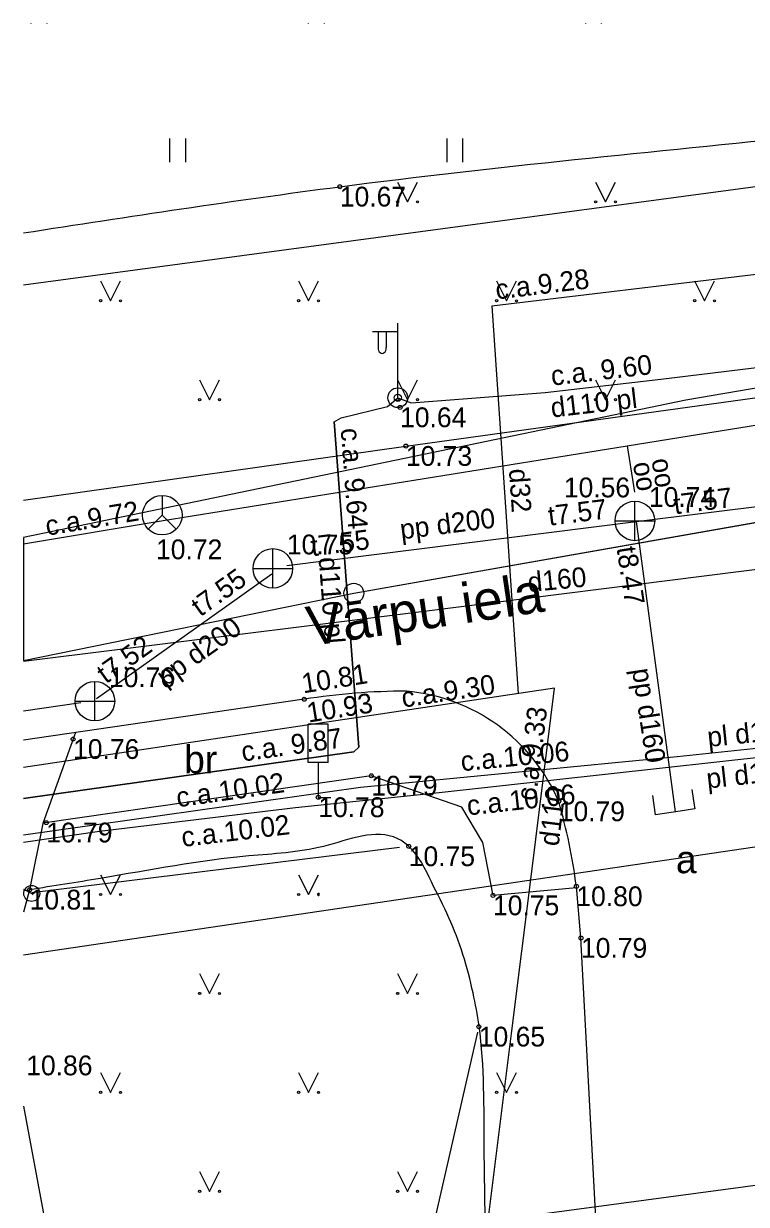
# Model space of a CAD drawing. Extents: x 502312.8 to 502402.4, y 308528.5 to 308602.
# Drawn here: x 502312.81 to 502331.06, y 308572.17 to 308602 of the extents above; entities that cross this region are included whole.
import ezdxf

# ---------------------------------------------------------------- set-up
doc = ezdxf.new("R2010")
doc.units = 0
for name, color, linetype in [('10', 7, 'Continuous'), ('24', 7, 'Continuous'), ('38', 7, 'Continuous'), ('APGR_SARK_####_####_#', 7, 'Continuous'), ('APGS_ACRL_####_####_#', 7, 'Continuous'), ('APGS_ACRL_####_TKST_#', 7, 'Continuous'), ('APGS_ELEM_####_####_#', 7, 'Continuous'), ('APGS_VADP_ZSPR_####_I', 7, 'Continuous'), ('CELI_CAPM_####_####_#', 7, 'Continuous'), ('CELI_CMAL_####_####_#', 7, 'Continuous'), ('CELI_CSEG_####_TKST_#', 7, 'Continuous'), ('CELI_ELEM_####_####_#', 7, 'Continuous'), ('CELI_IELA_####_TKST_#', 7, 'Continuous'), ('CELI_SEGL_####_####_#', 7, 'Continuous'), ('ELEK_ACRL_####_####_#', 7, 'Continuous'), ('ELEK_ACRL_####_TKST_#', 7, 'Continuous'), ('ELEK_VADP_VSPR_####_I', 7, 'Continuous'), ('ELEK_VADP_ZSPR_####_I', 7, 'Continuous'), ('GAZE_VADP_VSP2_####_#', 7, 'Continuous'), ('GAZE_VADP_VSP2_TKST_#', 7, 'Continuous'), ('NORB_ELEM_####_####_#', 7, 'Continuous'), ('NORB_ZOGS_BARJ_####_#', 7, 'Continuous'), ('NORB_ZOGS_ZSTP_####_#', 7, 'Continuous'), ('RELJ_AATZ_####_TKST_#', 7, 'Continuous'), ('RELJ_ELEM_####_####_#', 7, 'Continuous'), ('SAKK_ELEM_####_####_#', 7, 'Continuous'), ('SAKK_ELEM_####_TKST_#', 7, 'Continuous'), ('SAKK_IZVK_####_TKST_#', 7, 'Continuous'), ('SAKK_KKAN_####_####_#', 7, 'Continuous'), ('SAKK_KKAN_####_TKST_#', 7, 'Continuous'), ('SKAN_ELEM_####_####_#', 7, 'Continuous'), ('SKAN_ELEM_PAST_TKST_#', 7, 'Continuous'), ('SKAN_VADP_PAST_####_I', 7, 'Continuous'), ('SKAN_VADP_PAST_TKST_I', 7, 'Continuous'), ('TERT_ELEM_####_####_#', 7, 'Continuous'), ('TERT_KONT_####_####_#', 7, 'Continuous'), ('UDTK_VADP_UDEN_####_I', 7, 'Continuous'), ('UDTK_VADP_UDEN_TKST_I', 7, 'Continuous')]:
    doc.layers.add(name, color=color, linetype=linetype)

msp = doc.modelspace()

# ---------------------------------------------------------------- linework, layer by layer
at = {"layer": '10'}
msp.add_circle((502321.144, 308587.612), 0.25, dxfattribs=at)
at = {"layer": '24'}
for p, q in [((502321.144, 308587.612), (502337.181, 308590.44)), ((502312.806, 308585.911), (502321.144, 308587.612)), ((502335.708, 308581.855), (502312.806, 308578.464))]:
    msp.add_line(p, q, dxfattribs=at)
at = {"layer": '38'}
msp.add_line((502312.806, 308589.016), (502312.806, 308585.911), dxfattribs=at)
msp.add_lwpolyline([(502312.806, 308585.911), (502321.144, 308587.612), (502337.181, 308590.44), (502351.582, 308592.356), (502382.507, 308595.627), (502382.531, 308595.63), (502383.93, 308595.78), (502383.493, 308598.901), (502376.9, 308598.344), (502359.324, 308596.701), (502339.771, 308594.239), (502329.531, 308592.488), (502312.806, 308589.016)], dxfattribs=at)
at = {"layer": 'APGR_SARK_####_####_#'}
for p, q in [((502312.806, 308595.403), (502361.947, 308602.001)), ((502312.806, 308570.179), (502363.114, 308576.934))]:
    msp.add_line(p, q, dxfattribs=at)
at = {"layer": 'APGS_ACRL_####_####_#'}
msp.add_line((502325.976, 308592.683), (502328.899, 308593.021), dxfattribs=at)
msp.add_lwpolyline([(502320.647, 308591.944), (502321.27, 308583.722), (502321.142, 308583.604), (502312.806, 308582.421)], dxfattribs=at)
at = {"layer": 'APGS_ELEM_####_####_#'}
for p, q in [((502322.255, 308592.549), (502322.255, 308594.432)), ((502322.255, 308594.216), (502321.62, 308594.211)), ((502321.755, 308594.212), (502321.755, 308593.82)), ((502321.965, 308594.214), (502321.965, 308593.82))]:
    msp.add_line(p, q, dxfattribs=at)
for radius in [0.25, 0.09]:
    msp.add_circle((502322.255, 308592.549), radius, dxfattribs=at)
msp.add_ellipse((502321.86, 308593.82), major_axis=(0, 0.151), ratio=0.695971, start_param=1.570796, end_param=4.712389, dxfattribs=at)
at = {"layer": 'APGS_VADP_ZSPR_####_I'}
for p, q in [((502325.976, 308592.683), (502328.899, 308593.021)), ((502321.27, 308583.722), (502320.647, 308591.944))]:
    msp.add_line(p, q, dxfattribs=at)
for points in [[(502328.899, 308593.021), (502345.961, 308595.098), (502354.788, 308596.247), (502359.02, 308596.899)], [(502321.996, 308592.329), (502322.255, 308592.549), (502322.59, 308592.422)], [(502322.59, 308592.422), (502325.976, 308592.683)], [(502320.647, 308591.944), (502320.822, 308592.044), (502321.996, 308592.329)], [(502312.806, 308582.421), (502321.142, 308583.604), (502321.27, 308583.722)]]:
    msp.add_lwpolyline(points, dxfattribs=at)
at = {"layer": 'CELI_CAPM_####_####_#'}
for points in [[(502312.806, 308589.961), (502322.46, 308591.329), (502333.461, 308592.851), (502346.075, 308594.464), (502354.016, 308595.225), (502359.019, 308595.646), (502368.001, 308596.15), (502374.084, 308596.461), (502389.008, 308597.854), (502397.381, 308598.824), (502402.407, 308599.392)], [(502319.891, 308584.932), (502312.806, 308583.899)], [(502312.957, 308580.12), (502312.806, 308579.555)], [(502322.863, 308528.536), (502323.443, 308530.946), (502325.163, 308540.207), (502326.683, 308549.996), (502327.505, 308559.246), (502327.386, 308569.461), (502326.881, 308578.901), (502326.764, 308580.205)], [(502312.806, 308574.649), (502313.726, 308569.672), (502314.559, 308564.701), (502312.806, 308564.738)]]:
    msp.add_lwpolyline(points, dxfattribs=at)
for centre, radius, start, end in [((502322.492, 308568.529), 16.608, 90.0741, 99.0119), ((502322.065, 308580.526), 4.629, 23.2192, 84.9708), ((502311.98, 308578.258), 14.912, 7.5007, 15.9293)]:
    msp.add_arc(centre, radius, start, end, dxfattribs=at)
at = {"layer": 'CELI_CMAL_####_####_#'}
for points in [[(502314.114, 308584.09), (502313.289, 308581.796), (502312.957, 308580.12)], [(502326.769, 308580.165), (502324.659, 308579.975), (502324.4, 308581.314), (502323.874, 308582.21), (502321.585, 308582.998), (502313.291, 308581.803)]]:
    msp.add_lwpolyline(points, dxfattribs=at)
at = {"layer": 'CELI_ELEM_####_####_#'}
for p, q in [((502320.493, 308584.301), (502319.993, 308584.301)), ((502319.993, 308583.332), (502319.993, 308584.301)), ((502320.493, 308583.332), (502320.493, 308584.301)), ((502320.493, 308583.332), (502319.993, 308583.332)), ((502320.247, 308583.332), (502320.247, 308582.454)), ((502320.247, 308582.454), (502320.562, 308582.454))]:
    msp.add_line(p, q, dxfattribs=at)
at = {"layer": 'CELI_SEGL_####_####_#'}
msp.add_lwpolyline([(502312.806, 308580.102), (502312.957, 308580.12)], dxfattribs=at)
at = {"layer": 'ELEK_ACRL_####_####_#'}
for points in [[(502312.806, 308581.506), (502314.65, 308581.767), (502321.314, 308582.715), (502329.307, 308583.49), (502335.866, 308584.18), (502339.262, 308584.609), (502345.983, 308585.426), (502351.131, 308585.924)], [(502312.806, 308581.319), (502314.719, 308581.602), (502319.674, 308582.194), (502323.299, 308582.577), (502335.948, 308583.975), (502339.276, 308584.42), (502343.854, 308584.946)]]:
    msp.add_lwpolyline(points, dxfattribs=at)
at = {"layer": 'ELEK_VADP_VSPR_####_I'}
msp.add_lwpolyline([(502312.806, 308581.319), (502314.719, 308581.602), (502319.674, 308582.194), (502323.299, 308582.577), (502335.948, 308583.975), (502339.276, 308584.42), (502343.828, 308584.943)], dxfattribs=at)
at = {"layer": 'ELEK_VADP_ZSPR_####_I'}
msp.add_lwpolyline([(502312.806, 308581.506), (502314.65, 308581.767), (502321.314, 308582.715), (502329.307, 308583.49), (502335.866, 308584.18), (502339.262, 308584.609), (502345.983, 308585.426), (502351.131, 308585.924)], dxfattribs=at)
at = {"layer": 'GAZE_VADP_VSP2_####_#'}
msp.add_lwpolyline([(502312.806, 308585.897), (502315.165, 308586.191), (502322.988, 308587.165), (502330.855, 308588.157), (502338.722, 308589.148), (502339.59, 308589.258)], dxfattribs=at)
at = {"layer": 'NORB_ELEM_####_####_#'}
msp.add_circle((502313.01, 308580.025), 0.202, dxfattribs=at)
at = {"layer": 'NORB_ZOGS_BARJ_####_#'}
msp.add_lwpolyline([(502312.806, 308580.135), (502313.01, 308580.025)], dxfattribs=at)
at = {"layer": 'NORB_ZOGS_ZSTP_####_#'}
for points in [[(502322.296, 308581.187), (502313.015, 308580.038)], [(502313.304, 308528.536), (502319.831, 308557.078), (502324.272, 308576.524)]]:
    msp.add_lwpolyline(points, dxfattribs=at)
at = {"layer": 'RELJ_ELEM_####_####_#'}
for centre in [(502320.791, 308597.881), (502322.313, 308592.306), (502322.46, 308591.329), (502319.891, 308584.932), (502314.055, 308583.925), (502321.585, 308582.998), (502320.247, 308582.454), (502326.319, 308582.351), (502313.377, 308581.815), (502322.532, 308581.216), (502312.957, 308580.12), (502324.659, 308579.975), (502326.764, 308580.205), (502326.881, 308578.901), (502324.301, 308576.659)]:
    msp.add_circle(centre, 0.05, dxfattribs=at)
at = {"layer": 'SAKK_ELEM_####_####_#'}
msp.add_line((502316.308, 308589.582), (502316.662, 308589.228), dxfattribs=at)
msp.add_lwpolyline([(502316.308, 308590.082), (502316.308, 308589.582), (502315.954, 308589.228)], dxfattribs=at)
msp.add_circle((502316.308, 308589.582), 0.5, dxfattribs=at)
at = {"layer": 'SAKK_IZVK_####_TKST_#'}
msp.add_lwpolyline([(502328.047, 308591.335), (502328.236, 308590.164)], dxfattribs=at)
at = {"layer": 'SAKK_KKAN_####_####_#'}
msp.add_lwpolyline([(502312.806, 308588.858), (502316.332, 308589.448), (502328.047, 308591.335), (502333.737, 308592.252), (502339.284, 308592.792)], dxfattribs=at)
at = {"layer": 'SKAN_ELEM_####_####_#'}
for p, q in [((502328.242, 308588.938), (502328.242, 308589.938)), ((502327.742, 308589.438), (502328.742, 308589.438)), ((502319.099, 308587.738), (502319.099, 308588.738)), ((502318.599, 308588.238), (502319.599, 308588.238)), ((502314.605, 308584.384), (502314.605, 308585.384)), ((502314.105, 308584.884), (502315.105, 308584.884))]:
    msp.add_line(p, q, dxfattribs=at)
for points in [[(502329.384, 308582.104), (502328.766, 308582.01), (502328.691, 308582.505)], [(502329.68, 308582.654), (502329.74, 308582.256)], [(502329.74, 308582.256), (502329.754, 308582.16), (502329.384, 308582.104)]]:
    msp.add_lwpolyline(points, dxfattribs=at)
for centre in [(502328.242, 308589.438), (502319.099, 308588.238), (502314.605, 308584.884)]:
    msp.add_circle(centre, 0.5, dxfattribs=at)
at = {"layer": 'SKAN_VADP_PAST_####_I'}
msp.add_line((502328.277, 308589.419), (502339.455, 308590.813), dxfattribs=at)
for points in [[(502319.449, 308588.312), (502328.277, 308589.419)], [(502328.277, 308589.419), (502329.26, 308582.085)], [(502314.645, 308584.953), (502319.076, 308588.103)], [(502312.806, 308584.638), (502314.25, 308584.852)]]:
    msp.add_lwpolyline(points, dxfattribs=at)
at = {"layer": 'TERT_ELEM_####_####_#'}
for p, q in [((502313, 308602), (502313, 308602.001)), ((502313.4, 308602), (502313.4, 308602.001)), ((502320, 308602), (502320, 308602.001)), ((502320.4, 308602), (502320.4, 308602.001)), ((502327, 308602), (502327, 308602.001)), ((502327.4, 308602), (502327.4, 308602.001)), ((502316.5, 308598.5), (502316.5, 308599.1)), ((502316.9, 308598.5), (502316.9, 308599.1)), ((502323.5, 308598.5), (502323.5, 308599.1)), ((502323.9, 308598.5), (502323.9, 308599.1)), ((502322.25, 308598), (502322.5, 308597.5)), ((502322.5, 308597.5), (502322.75, 308598)), ((502327.25, 308598), (502327.5, 308597.5)), ((502327.5, 308597.5), (502327.75, 308598)), ((502314.75, 308595.5), (502315, 308595)), ((502315, 308595), (502315.25, 308595.5)), ((502319.75, 308595.5), (502320, 308595)), ((502320, 308595), (502320.25, 308595.5)), ((502324.75, 308595.5), (502325, 308595)), ((502325, 308595), (502325.25, 308595.5)), ((502329.75, 308595.5), (502330, 308595)), ((502330, 308595), (502330.25, 308595.5)), ((502317.25, 308593), (502317.5, 308592.5)), ((502317.5, 308592.5), (502317.75, 308593)), ((502322.25, 308593), (502322.5, 308592.5)), ((502322.5, 308592.5), (502322.75, 308593)), ((502327.25, 308593), (502327.5, 308592.5)), ((502327.5, 308592.5), (502327.75, 308593)), ((502314.75, 308580.5), (502315, 308580)), ((502315, 308580), (502315.25, 308580.5)), ((502319.75, 308580.5), (502320, 308580)), ((502320, 308580), (502320.25, 308580.5)), ((502320.271, 308579.985), (502320.232, 308579.98)), ((502320.232, 308579.98), (502320.271, 308579.985)), ((502317.25, 308578), (502317.5, 308577.5)), ((502317.5, 308577.5), (502317.75, 308578)), ((502322.25, 308578), (502322.5, 308577.5)), ((502322.5, 308577.5), (502322.75, 308578)), ((502314.75, 308575.5), (502315, 308575)), ((502315, 308575), (502315.25, 308575.5)), ((502319.75, 308575.5), (502320, 308575)), ((502320, 308575), (502320.25, 308575.5)), ((502324.75, 308575.5), (502325, 308575)), ((502325, 308575), (502325.25, 308575.5)), ((502317.25, 308573), (502317.5, 308572.5)), ((502317.5, 308572.5), (502317.75, 308573)), ((502322.25, 308573), (502322.5, 308572.5)), ((502322.5, 308572.5), (502322.75, 308573))]:
    msp.add_line(p, q, dxfattribs=at)
for centre, radius in [((502322.25, 308597.5), 0.028), ((502322.75, 308597.5), 0.0263), ((502327.25, 308597.5), 0.028), ((502327.75, 308597.5), 0.0263), ((502314.75, 308595), 0.028), ((502315.25, 308595), 0.0263), ((502319.75, 308595), 0.028), ((502320.25, 308595), 0.0263), ((502324.75, 308595), 0.028), ((502325.25, 308595), 0.0263), ((502329.75, 308595), 0.028), ((502330.25, 308595), 0.0263), ((502317.25, 308592.5), 0.028), ((502317.75, 308592.5), 0.0263), ((502322.25, 308592.5), 0.028), ((502322.75, 308592.5), 0.0263), ((502327.25, 308592.5), 0.028), ((502327.75, 308592.5), 0.0263), ((502314.75, 308580), 0.028), ((502315.25, 308580), 0.0263), ((502319.75, 308580), 0.028), ((502317.25, 308577.5), 0.028), ((502317.75, 308577.5), 0.0263), ((502322.25, 308577.5), 0.028), ((502322.75, 308577.5), 0.0263), ((502314.75, 308575), 0.028), ((502315.25, 308575), 0.0263), ((502319.75, 308575), 0.028), ((502320.25, 308575), 0.0263), ((502324.75, 308575), 0.028), ((502325.25, 308575), 0.0263), ((502317.25, 308572.5), 0.028), ((502317.75, 308572.5), 0.0263), ((502322.25, 308572.5), 0.028), ((502322.75, 308572.5), 0.0263)]:
    msp.add_circle(centre, radius, dxfattribs=at)
for start, end in [(325.6754, 228.3927), (228.3927, 325.6754)]:
    msp.add_arc((502320.25, 308580), 0.0263, start, end, dxfattribs=at)
at = {"layer": 'TERT_KONT_####_####_#'}
for points in [[(502312.806, 308596.715), (502320.791, 308597.881), (502332.656, 308599.172), (502344.523, 308600.445), (502359.328, 308602.001)], [(502318.205, 308528.536), (502319.679, 308534.76), (502321.307, 308542.669), (502322.012, 308546.644), (502322.648, 308550.634), (502323.554, 308557.442), (502324.228, 308564.274), (502324.421, 308567.369), (502324.483, 308570.471), (502324.437, 308573.576), (502324.307, 308576.676), (502324.156, 308577.514), (502323.545, 308579.414), (502323.104, 308580.32), (502322.532, 308581.216), (502322.254, 308581.408), (502320.377, 308581.216), (502318.497, 308580.974), (502314.744, 308580.405), (502312.957, 308580.12)]]:
    msp.add_spline(points, degree=3, dxfattribs=at)
at = {"layer": 'UDTK_VADP_UDEN_####_I'}
msp.add_line((502322.212, 308553.122), (502325.125, 308576.488), dxfattribs=at)
for points in [[(502324.63, 308594.872), (502351.064, 308598.035), (502366.307, 308598.312), (502381.551, 308598.59), (502384.121, 308597.913)], [(502324.63, 308594.872), (502325.297, 308585.075)], [(502325.644, 308580.648), (502326.213, 308585.212), (502312.806, 308583.206)], [(502325.125, 308576.488), (502325.644, 308580.648)]]:
    msp.add_lwpolyline(points, dxfattribs=at)

# ---------------------------------------------------------------- texts
at = {"layer": 'APGS_ACRL_####_TKST_#'}
for s, rotation, p in [('c.a. 9.60', 6.5961, (502326.15, 308592.854)), ('d110 pl', 6.5961, (502326.145, 308592.048)), ('c.a. 9.64', 274.3332, (502320.811, 308591.769)), ('d110 pl', 274.3332, (502320.255, 308588.51)), ('c.a. 9.87', 8.0745, (502318.339, 308583.358))]:
    msp.add_text(s, height=0.5, rotation=rotation, dxfattribs=at).set_placement(p)
at = {"layer": 'CELI_CSEG_####_TKST_#'}
for s, p in [('br', (502316.861, 308583.062)), ('a', (502329.278, 308580.538))]:
    msp.add_text(s, height=0.7, dxfattribs=at).set_placement(p)
at = {"layer": 'CELI_IELA_####_TKST_#'}
msp.add_text('Vārpu iela', height=1, rotation=8.4121, dxfattribs=at).set_placement((502320.036, 308586.272))
at = {"layer": 'ELEK_ACRL_####_TKST_#'}
for s, rotation, p in [('pl d160', 6.0029, (502330.096, 308583.724)), ('c.a.10.06', 5.5355, (502323.867, 308583.113)), ('pl d160', 6.3056, (502330.075, 308582.675)), ('c.a.10.02', 8.1008, (502316.698, 308582.201)), ('c.a.10.06', 6.3056, (502324.027, 308581.996)), ('c.a.10.02', 6.8088, (502316.82, 308581.2))]:
    msp.add_text(s, height=0.5, rotation=rotation, dxfattribs=at).set_placement(p)
at = {"layer": 'GAZE_VADP_VSP2_TKST_#'}
msp.add_text('d160', height=0.5, rotation=5.6118, dxfattribs=at).set_placement((502325.558, 308587.636))
at = {"layer": 'RELJ_AATZ_####_TKST_#'}
for s, p in [('10.67', (502320.791, 308597.381)), ('10.64', (502322.313, 308591.806)), ('10.73', (502322.46, 308590.829)), ('10.76', (502314.055, 308583.425)), ('10.79', (502321.585, 308582.498)), ('10.78', (502320.247, 308581.954)), ('10.79', (502326.319, 308581.851)), ('10.79', (502313.377, 308581.315)), ('10.75', (502322.532, 308580.716)), ('10.81', (502312.957, 308579.62)), ('10.80', (502326.764, 308579.705)), ('10.75', (502324.659, 308579.475)), ('10.79', (502326.881, 308578.401)), ('10.65', (502324.301, 308576.159)), ('10.86', (502312.872, 308575.432))]:
    msp.add_text(s, height=0.5, dxfattribs=at).set_placement(p)
for s, p in [('10.81', (502319.868, 308585.08)), ('10.93', (502319.999, 308584.342))]:
    msp.add_text(s, height=0.5, rotation=9.0119, dxfattribs=at).set_placement(p)
at = {"layer": 'SAKK_ELEM_####_TKST_#'}
msp.add_text('10.72', height=0.5, dxfattribs=at).set_placement((502316.149, 308588.469))
at = {"layer": 'SAKK_IZVK_####_TKST_#'}
for p in [(502328.191, 308590.894), (502328.659, 308590.984)]:
    msp.add_text('oo', height=0.5, rotation=279.1519, dxfattribs=at).set_placement(p)
at = {"layer": 'SAKK_KKAN_####_TKST_#'}
msp.add_text('c.a.9.72', height=0.5, rotation=9.4954, dxfattribs=at).set_placement((502313.399, 308589.063))
at = {"layer": 'SKAN_ELEM_PAST_TKST_#'}
for s, p in [(' 10.56', (502326.262, 308590.033)), ('10.74', (502328.596, 308589.792)), ('10.75', (502319.453, 308588.592)), ('10.76', (502314.959, 308585.238))]:
    msp.add_text(s, height=0.5, dxfattribs=at).set_placement(p)
at = {"layer": 'SKAN_VADP_PAST_TKST_I'}
for s, rotation, p in [('t7.57', 7.2516, (502329.251, 308589.604)), ('t7.57', 7.1923, (502326.082, 308589.315)), ('pp d200', 7.1923, (502322.341, 308588.969)), ('t7.55', 7.1923, (502320.089, 308588.544)), ('t8.47', 278.5854, (502327.779, 308588.755)), ('t7.55', 35.409, (502317.268, 308587.002)), ('pp d200', 35.409, (502316.385, 308585.236)), ('t7.52', 35.409, (502314.884, 308585.307)), ('pp d160', 278.5854, (502328.168, 308585.684))]:
    msp.add_text(s, height=0.5, rotation=rotation, dxfattribs=at).set_placement(p)
at = {"layer": 'UDTK_VADP_UDEN_TKST_I'}
for s, rotation, p in [('c.a.9.28', 6.8234, (502324.75, 308595.032)), ('d32', 273.8971, (502325.061, 308590.745)), ('c.a.9.30', 8.5077, (502322.386, 308584.72)), ('c.a.9.33', 82.8936, (502325.737, 308582.35)), ('d110', 82.8936, (502326.314, 308581.204))]:
    msp.add_text(s, height=0.5, rotation=rotation, dxfattribs=at).set_placement(p)

doc.saveas('drawing.dxf')
